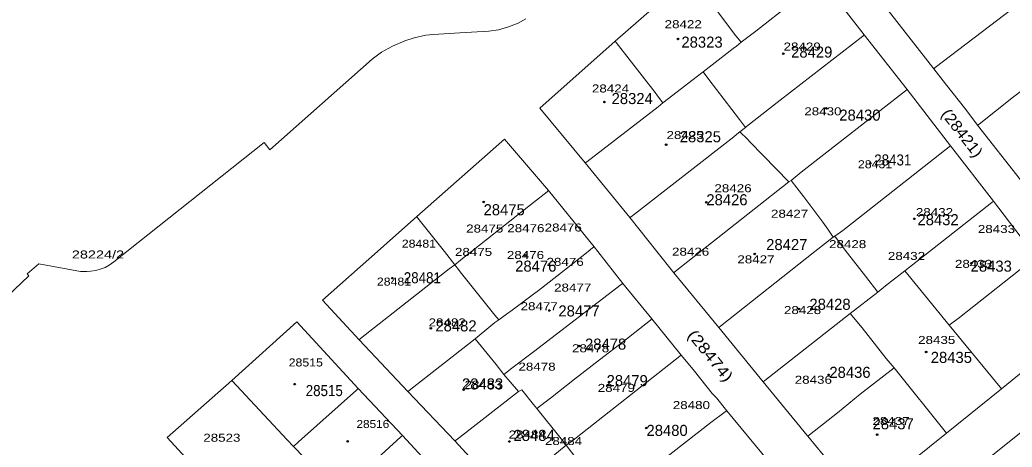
# Model space of a CAD drawing. Extents: x 650553 to 652508, y 239277 to 241647.
# Drawn here: x 651208.2 to 651530.5, y 240936.5 to 241075.2 of the extents above; entities that cross this region are included whole.
import ezdxf

# ---------------------------------------------------------------- set-up
doc = ezdxf.new("R2010")
doc.units = 0
doc.header["$PDMODE"] = 32
doc.header["$PDSIZE"] = 0.5
for name, color, linetype in [('19', 7, 'Continuous'), ('20', 7, 'Continuous'), ('6', 7, 'Continuous')]:
    doc.layers.add(name, color=color, linetype=linetype)
doc.layers.add('3', color=7, linetype='Continuous', lineweight=13)
doc.layers.add('5', color=7, linetype='Continuous', lineweight=13)

msp = doc.modelspace()

# ---------------------------------------------------------------- linework, layer by layer
at = {"layer": '3'}
for points in [[(651425.97, 241089.77), (651450.48, 241111.43), (651468.64, 241088.17), (651482.45, 241070.35), (651496.33, 241052.57), (651510.47, 241034.36), (651524.41, 241016.3)], [(651519.26, 241040.99), (651515.47, 241046.09), (651508.81, 241054.48), (651505.02, 241059.33), (651491.06, 241077.17), (651477.24, 241094.86)], [(651391.8, 241028.75), (651377.07, 241046.59), (651401.51, 241068.33), (651425.97, 241089.77)], [(651197.1, 240978.93), (651211.069, 240992.128), (651210.543, 240992.719), (651214.368, 240995.945), (651227.85, 240993.48), (651229.88, 240993.5), (651231.24, 240993.57), (651232.79, 240993.83), (651234.19, 240994.32), (651235.82, 240994.79), (651237.17, 240995.56), (651238.68, 240996.6), (651242.95, 241000), (651287.489, 241035.354), (651289.389, 241032.994), (651322.58, 241062.41), (651325.66, 241064.78), (651329.15, 241066.68), (651333.18, 241068.41), (651336.22, 241069.4), (651340.05, 241070.26), (651342.38, 241070.42), (651351.1, 241071.02), (651360.44, 241071.58), (651363.67, 241072.02), (651366.89, 241072.98), (651370, 241074.13), (651372.52, 241075.56)], [(651582.04, 241000), (651565, 240985.97), (651561.78, 240986.38), (651551.43, 241000), (651547.43, 241005.26), (651533.21, 241023.25), (651519.26, 241040.99)], [(651318.32, 240971.34), (651306.46, 240984.22), (651324.32, 241000), (651337.08, 241011.34), (651365.6, 241036.51)], [(651365.6, 241036.51), (651379.89, 241019.77), (651394.68, 241001.55)], [(651420.56, 240993.12), (651415.08, 241000), (651406.31, 241011), (651391.8, 241028.75)], [(651524.41, 241016.3), (651536.85, 241000), (651538.21, 240998.22)], [(651394.68, 241001.55), (651395.89, 241000), (651403.99, 240989.62), (651413.47, 240978.14), (651423.01, 240966.38)], [(651538.21, 240998.22), (651553.74, 240978.64), (651553.52, 240976.92), (651526.98, 240955.44), (651509.19, 240941.06)], [(651464.1, 240940.04), (651463.39, 240940.94), (651461.54, 240943.13), (651449.59, 240957.71), (651435.2, 240975.32), (651420.56, 240993.12)], [(651277, 240958.16), (651298.11, 240977.12), (651318.05, 240955.47), (651332.44, 240940.26), (651346.55, 240924.99), (651356.03, 240914.24), (651366.39, 240902.79)], [(651380.56, 240904.16), (651375, 240910.37), (651369.11, 240916.96), (651365.03, 240921.5), (651349.46, 240938.51), (651334.15, 240954.49), (651318.32, 240971.34)], [(651423.01, 240966.38), (651425.76, 240963.01), (651427.33, 240961.17), (651433.07, 240953.92), (651434.4, 240952.52), (651437.75, 240948.31)], [(651279.96, 240913.54), (651256.05, 240939.64), (651277, 240958.16)], [(651546.27, 240951.81), (651531.67, 240939.91), (651516.66, 240927.91), (651501.92, 240915.97)], [(651437.75, 240948.31), (651469.83, 240909.51), (651430.38, 240877.39)], [(651509.19, 240941.06), (651481.51, 240918.86), (651464.1, 240940.04)]]:
    msp.add_lwpolyline(points, dxfattribs=at)
at = {"layer": '5'}
for p, q in [((651472.39, 241004.71), (651466.43, 241000)), ((651472.92, 241004.97), (651476.55, 241000)), ((651349.45, 240995.68), (651346.04, 241000)), ((651353.57, 240999.03), (651354.81, 241000)), ((651349.45, 240995.68), (651350.67, 240994.13)), ((651363.78, 240977.84), (651362.44, 240976.94)), ((651510.07, 240976.11), (651513.35, 240978.58)), ((651385.61, 240937.08), (651387.37, 240938.34))]:
    msp.add_line(p, q, dxfattribs=at)
for points in [[(651447.23, 241071.56), (651442.48, 241067.94), (651440.75, 241070.06), (651425.97, 241089.77)], [(651545.7, 241090.47), (651505.52, 241059.713), (651505.02, 241059.33)], [(651468.64, 241088.17), (651468.14, 241087.788), (651458.84, 241080.69), (651447.23, 241071.56)], [(651455.09, 241049.12), (651481.95, 241069.962), (651482.45, 241070.35)], [(651519.26, 241040.99), (651519.76, 241041.387), (651530.89, 241050.22), (651540.19, 241057.3), (651543.85, 241060.18), (651560.44, 241073)], [(651414.51, 241051.68), (651401.9, 241067.83), (651401.51, 241068.33)], [(651442.48, 241067.94), (651440.96, 241066.72), (651439.84, 241065.88), (651430.09, 241058.35), (651431.94, 241055.91)], [(651430.09, 241058.35), (651427.86, 241056.62), (651420.25, 241050.72), (651417, 241048.31), (651415.54, 241047.01)], [(651443.86, 241040.28), (651441.96, 241042.83), (651431.94, 241055.91)], [(651417, 241048.31), (651415.3, 241050.6), (651414.51, 241051.68)], [(651496.33, 241052.57), (651495.83, 241052.179), (651461.99, 241025.74), (651458.68, 241023.1), (651457.99, 241022.64), (651429.28, 241000)], [(651442.02, 241038.86), (651443.86, 241040.28), (651444.24, 241040.56), (651455.09, 241049.12)], [(651415.54, 241047.01), (651392.3, 241029.135), (651391.8, 241028.75)], [(651457.99, 241022.64), (651445.43, 241035.51), (651444.52, 241036.45), (651442.02, 241038.86), (651441.72, 241038.6), (651440.03, 241037.27)], [(651440.03, 241037.27), (651406.81, 241011.39), (651406.31, 241011)], [(651510.47, 241034.36), (651509.97, 241033.967), (651475.48, 241006.86)], [(651458.68, 241023.1), (651460.59, 241020.63), (651462.8, 241017.76), (651468.96, 241009.48), (651470.62, 241007.29), (651472.39, 241004.71), (651472.92, 241004.97), (651475.48, 241006.86)], [(651379.89, 241019.77), (651379.39, 241019.376), (651375, 241015.92)], [(651375, 241015.92), (651369.95, 241011.92), (651354.81, 241000)], [(651524.41, 241016.3), (651523.91, 241015.907), (651503.66, 241000)], [(651337.08, 241011.34), (651337.475, 241010.84), (651346.04, 241000)], [(651392.72, 241000), (651385.05, 240993.92), (651376.63, 240987.37), (651375, 240986.16)], [(651394.68, 241001.55), (651394.18, 241001.155), (651392.72, 241000)], [(651420.56, 240993.12), (651421.06, 240993.514), (651429.28, 241000)], [(651435.2, 240975.32), (651435.7, 240975.715), (651466.43, 241000)], [(651477.81, 240979.86), (651486.81, 240986.85), (651482.85, 240992.04), (651476.95, 240999.45), (651476.55, 241000)], [(651486.81, 240986.85), (651489.29, 240988.87), (651495.61, 240993.68), (651503.66, 241000)], [(651318.32, 240971.34), (651318.82, 240971.732), (651347.66, 240994.35), (651349.45, 240995.68), (651351.25, 240997.2), (651353.57, 240999.03)], [(651513.35, 240978.58), (651537.71, 240997.825), (651538.21, 240998.22)], [(651350.67, 240994.13), (651351.23, 240993.4), (651362.48, 240979.31)], [(651495.61, 240993.68), (651510.07, 240976.11), (651511.59, 240974.25)], [(651375, 240967.47), (651403.49, 240989.238), (651403.99, 240989.62)], [(651362.48, 240979.31), (651363.78, 240977.84), (651366.22, 240979.64), (651368.08, 240980.98), (651375, 240986.16)], [(651449.59, 240957.71), (651450.09, 240958.102), (651477.81, 240979.86), (651481.78, 240975.22), (651489.53, 240965.27), (651492.19, 240962.21), (651509.19, 240941.06)], [(651362.44, 240976.94), (651361.14, 240975.81), (651356, 240971.69)], [(651404.31, 240970.85), (651412.97, 240977.742), (651413.47, 240978.14)], [(651511.59, 240974.25), (651526.571, 240955.94), (651526.98, 240955.44)], [(651356, 240971.69), (651334.65, 240954.884), (651334.15, 240954.49)], [(651370.12, 240954.52), (651365.41, 240960.11), (651362.88, 240963.29), (651356, 240971.69)], [(651376.03, 240949.01), (651380.49, 240952.36), (651388.29, 240958.5), (651396.42, 240964.77), (651404.31, 240970.85)], [(651365.41, 240960.11), (651366.87, 240961.25), (651367.53, 240961.76), (651375, 240967.47)], [(651387.37, 240938.34), (651422.51, 240965.987), (651423.01, 240966.38)], [(651492.19, 240962.21), (651481.1, 240953.62), (651473.77, 240947.62)], [(651277, 240958.16), (651294.99, 240938.81), (651297.06, 240936.72), (651298.72, 240938.16)], [(651298.72, 240938.16), (651317.55, 240955.022), (651318.05, 240955.47)], [(651349.46, 240938.51), (651349.96, 240938.897), (651370.12, 240954.52), (651371.18, 240955.1), (651375, 240950.3)], [(651375, 240950.3), (651376.03, 240949.01), (651383.94, 240939.18), (651385.61, 240937.08)], [(651437.75, 240948.31), (651437.25, 240947.935), (651432.63, 240944.47)], [(651473.77, 240947.62), (651464.6, 240940.432), (651464.1, 240940.04)], [(651397.68, 240917.22), (651399.98, 240918.99), (651432.63, 240944.47)], [(651311.58, 240921.24), (651331.94, 240939.804), (651332.44, 240940.26)], [(651297.06, 240936.72), (651300.53, 240933.07), (651300.98, 240932.48), (651302.55, 240930.74), (651299.76, 240928.68), (651299.1, 240928.23)], [(651399.98, 240918.99), (651396.6, 240923.39), (651389.13, 240932.6), (651385.61, 240937.08), (651381.24, 240933.55), (651375, 240928.91)]]:
    msp.add_lwpolyline(points, dxfattribs=at)
at = {"layer": '6'}
for p in [(651421.951, 241069.04), (651456.127, 241064.225), (651398.046, 241048.54), (651470.159, 241046.495), (651418.101, 241034.675), (651484.447, 241028.64), (651358.845, 241016.095), (651431.136, 241015.99), (651498.703, 241010.605), (651372.249, 240998.805), (651446.855, 240999.21), (651517.243, 240996.205), (651329.17, 240991.34), (651380.179, 240980.83), (651461.267, 240981.34), (651341.665, 240975.085), (651389.866, 240969.315), (651502.557, 240967.37), (651297.434, 240956.92), (651399.511, 240957.61), (651470.858, 240959.95), (651352.278, 240955.1), (651411.618, 240942.685), (651314.644, 240938.355), (651367.146, 240938.3), (651486.633, 240940.535)]:
    msp.add_point(p, dxfattribs=at)

# ---------------------------------------------------------------- texts
at = {"layer": '19'}
for s, p in [('28323', (651423.044, 241066.191)), ('28429', (651458.683, 241062.958)), ('28324', (651400.365, 241047.871)), ('28430', (651474.342, 241042.483)), ('28325', (651422.504, 241035.478)), ('28426', (651431.144, 241015.003)), ('28475', (651358.788, 241011.77)), ('28432', (651499.718, 241008.537)), ('28427', (651450.583, 241000.455)), ('28476', (651369.049, 240993.45)), ('28433', (651516.997, 240993.45)), ('28428', (651464.621, 240981.057)), ('28477', (651383.088, 240978.902)), ('28482', (651343.129, 240974.053)), ('28478', (651391.726, 240968.125)), ('28435', (651504.038, 240963.815)), ('28436', (651471.101, 240958.965)), ('28483', (651351.769, 240955.194)), ('28479', (651398.747, 240956.271)), ('28437', (651485.14, 240942.262)), ('28484', (651368.508, 240938.491)), ('28480', (651411.705, 240940.107))]:
    msp.add_text(s, height=3.6, dxfattribs=at).set_placement(p)
for s, rotation, width, p in [('(28421)', 307.829, 1.1, (651507.231, 241044.596)), ('(28474)', 309.05, 1.2, (651424.808, 240972.775))]:
    msp.add_text(s, height=3.6, rotation=rotation, dxfattribs=dict(at, width=width)).set_placement(p)
at = {"layer": '19', "width": 0.9}
for s, p in [('28431', (651485.681, 241027.934)), ('28481', (651332.87, 240989.679)), ('28515', (651301.011, 240953.038))]:
    msp.add_text(s, height=3.6, dxfattribs=at).set_placement(p)
at = {"layer": '20'}
for s, width, p in [('28422', 1.25, (651417.598, 241072.519)), ('28429', 1.25, (651456.229, 241065.265)), ('28424', 1.25, (651393.973, 241051.644)), ('28430', 1.25, (651462.96, 241044.228)), ('28425', 1.25, (651418.207, 241036.521)), ('28431', 1.15, (651480.385, 241027.037)), ('28426', 1.25, (651433.765, 241019.243)), ('28427', 1.25, (651452.145, 241010.971)), ('28432', 1.25, (651499.21, 241011.49)), ('28475', 1.25, (651353.121, 241006.162)), ('28476', 1.25, (651366.48, 241006.276)), ('28476', 1.25, (651378.62, 241006.492)), ('28433', 1.25, (651519.331, 241006.011)), ('28481', 1.15, (651332.225, 241001.251)), ('28428', 1.25, (651471.001, 241001.099)), ('28224/2', 1.35, (651225.044, 240997.733)), ('28475', 1.25, (651349.49, 240998.574)), ('28476', 1.25, (651366.354, 240997.569)), ('28426', 1.25, (651419.993, 240998.64)), ('28432', 1.25, (651490.117, 240997.263)), ('28476', 1.25, (651379.234, 240995.343)), ('28427', 1.25, (651441.214, 240996.152)), ('28433', 1.25, (651511.904, 240994.689)), ('28481', 1.15, (651324.126, 240988.93)), ('28477', 1.25, (651381.692, 240986.986)), ('28477', 1.25, (651370.807, 240980.932)), ('28428', 1.25, (651456.362, 240979.678)), ('28482', 1.25, (651340.928, 240975.67)), ('28435', 1.25, (651499.929, 240969.979)), ('28478', 1.25, (651387.505, 240967.283)), ('28515', 1.15, (651295.473, 240962.664)), ('28478', 1.25, (651370.104, 240961.314)), ('28483', 1.25, (651352.587, 240955.421)), ('28436', 1.25, (651459.855, 240957.053)), ('28479', 1.25, (651395.866, 240954.412)), ('28480', 1.25, (651420.246, 240948.829)), ('28516', 1.1, (651317.503, 240942.689)), ('28437', 1.25, (651485.109, 240943.668)), ('28484', 1.25, (651366.924, 240939.271)), ('28523', 1.25, (651267.734, 240938.223)), ('28484', 1.25, (651378.711, 240937.155))]:
    msp.add_text(s, height=2.6, dxfattribs=dict(at, width=width)).set_placement(p)

doc.saveas('drawing.dxf')
